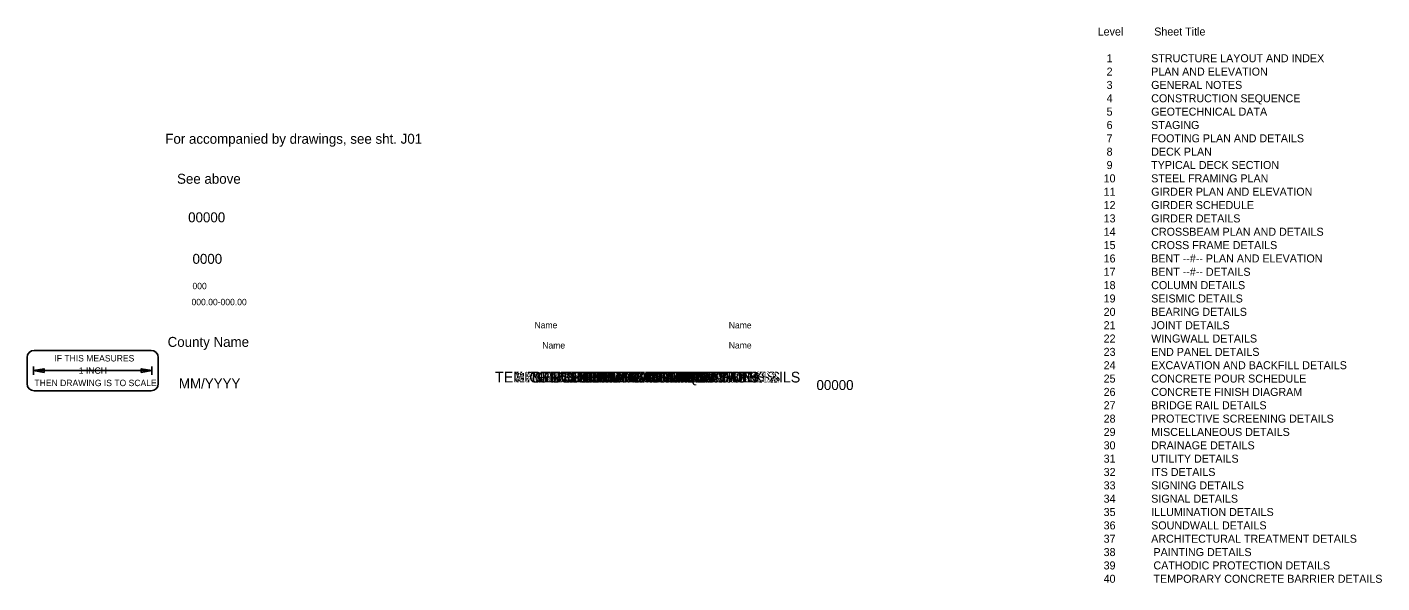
# Model space of a CAD drawing. Extents: x 0.799 to 1.751, y -0.088 to 0.302.
import ezdxf

# ---------------------------------------------------------------- set-up
doc = ezdxf.new("R2010")
doc.units = 0
for name, color, linetype in [('Level 1', 7, 'Continuous'), ('Level 10', 7, 'Continuous'), ('Level 11', 7, 'Continuous'), ('Level 12', 7, 'Continuous'), ('Level 13', 7, 'Continuous'), ('Level 14', 7, 'Continuous'), ('Level 15', 7, 'Continuous'), ('Level 16', 7, 'Continuous'), ('Level 17', 7, 'Continuous'), ('Level 18', 7, 'Continuous'), ('Level 19', 7, 'Continuous'), ('Level 2', 7, 'Continuous'), ('Level 20', 7, 'Continuous'), ('Level 21', 7, 'Continuous'), ('Level 22', 7, 'Continuous'), ('Level 23', 7, 'Continuous'), ('Level 24', 7, 'Continuous'), ('Level 25', 7, 'Continuous'), ('Level 26', 7, 'Continuous'), ('Level 27', 7, 'Continuous'), ('Level 28', 7, 'Continuous'), ('Level 29', 7, 'Continuous'), ('Level 3', 7, 'Continuous'), ('Level 30', 7, 'Continuous'), ('Level 31', 7, 'Continuous'), ('Level 32', 7, 'Continuous'), ('Level 33', 7, 'Continuous'), ('Level 34', 7, 'Continuous'), ('Level 35', 7, 'Continuous'), ('Level 36', 7, 'Continuous'), ('Level 37', 7, 'Continuous'), ('Level 38', 7, 'Continuous'), ('Level 39', 7, 'Continuous'), ('Level 4', 7, 'Continuous'), ('Level 40', 7, 'Continuous'), ('Level 5', 7, 'Continuous'), ('Level 6', 7, 'Continuous'), ('Level 62', 7, 'Continuous'), ('Level 7', 7, 'Continuous'), ('Level 8', 7, 'Continuous'), ('Level 9', 7, 'Continuous'), ('P_ODOT_PLAN_General', 7, 'Continuous'), ('P_ODOT_PLAN_TBBDSDwg', 7, 'Continuous'), ('P_ODOT_PLAN_TBBgStrInfo', 7, 'Continuous'), ('P_ODOT_PLAN_TBlock', 7, 'Continuous'), ('P_ODOT_PLAN_TBShtDwgNo', 7, 'Continuous'), ('P_ODOT_PLAN_TeamNames', 7, 'Continuous')]:
    doc.layers.add(name, color=color, linetype=linetype)

msp = doc.modelspace()

# ---------------------------------------------------------------- linework, layer by layer
at = {"layer": 'P_ODOT_PLAN_General'}
for p, q in [((0.7987, 0.07), (0.7987, 0.05167)), ((0.88587, 0.075), (0.8037, 0.075)), ((0.89087, 0.05167), (0.89087, 0.07)), ((0.80311, 0.06383), (0.80311, 0.05783)), ((0.80311, 0.06083), (0.88645, 0.06083)), ((0.80311, 0.06083), (0.80311, 0.06083)), ((0.88645, 0.06383), (0.88645, 0.05783)), ((0.88645, 0.06083), (0.88645, 0.06083)), ((0.8037, 0.04667), (0.88587, 0.04667))]:
    msp.add_line(p, q, dxfattribs=at)
for points in [[(0.80311, 0.06083), (0.81061, 0.06208), (0.81061, 0.05958)], [(0.88645, 0.06083), (0.87895, 0.05958), (0.87895, 0.06208)]]:
    msp.add_lwpolyline(points, close=True, dxfattribs=at)
for centre, start, end in [((0.8037, 0.07), 90, 180), ((0.88587, 0.07), 360, 90), ((0.8037, 0.05167), 180, 270), ((0.88587, 0.05167), 270, 360)]:
    msp.add_arc(centre, 0.005, start, end, dxfattribs=at)

# ---------------------------------------------------------------- texts
at = {"layer": 'Level 1'}
msp.add_text('STRUCTURE LAYOUT AND INDEX', height=0.0075, dxfattribs=at).set_placement((1.1535, 0.0525))
at = {"layer": 'Level 10'}
msp.add_text('STEEL FRAMING PLAN', height=0.0075, dxfattribs=at).set_placement((1.17772, 0.0525))
at = {"layer": 'Level 11'}
msp.add_text('GIRDER PLAN AND ELEVATION', height=0.0075, dxfattribs=at).set_placement((1.15768, 0.0525))
at = {"layer": 'Level 12'}
msp.add_text('GIRDER SCHEDULE', height=0.0075, dxfattribs=at).set_placement((1.18503, 0.0525))
at = {"layer": 'Level 13'}
msp.add_text('GIRDER DETAILS', height=0.0075, dxfattribs=at).set_placement((1.19064, 0.0525))
at = {"layer": 'Level 14'}
msp.add_text('CROSSBEAM PLAN AND DETAILS', height=0.0075, dxfattribs=at).set_placement((1.15166, 0.0525))
at = {"layer": 'Level 15'}
msp.add_text('CROSS FRAME DETAILS', height=0.0075, dxfattribs=at).set_placement((1.17397, 0.0525))
at = {"layer": 'Level 16'}
msp.add_text('BENT   #   PLAN AND ELEVATION', height=0.0075, dxfattribs=at).set_placement((1.15357, 0.0525))
at = {"layer": 'Level 17'}
msp.add_text('BENT   #   DETAILS', height=0.0075, dxfattribs=at).set_placement((1.18653, 0.0525))
at = {"layer": 'Level 18'}
msp.add_text('COLUMN DETAILS', height=0.0075, dxfattribs=at).set_placement((1.1885, 0.0525))
at = {"layer": 'Level 19'}
msp.add_text('SEISMIC DETAILS', height=0.0075, dxfattribs=at).set_placement((1.18948, 0.0525))
at = {"layer": 'Level 2'}
msp.add_text('PLAN AND ELEVATION', height=0.0075, dxfattribs=at).set_placement((1.17813, 0.0525))
at = {"layer": 'Level 20'}
msp.add_text('BEARING DETAILS', height=0.0075, dxfattribs=at).set_placement((1.18747, 0.0525))
at = {"layer": 'Level 21'}
msp.add_text('JOINT DETAILS', height=0.0075, dxfattribs=at).set_placement((1.1961, 0.0525))
at = {"layer": 'Level 22'}
msp.add_text('WINGWALL DETAILS', height=0.0075, dxfattribs=at).set_placement((1.18198, 0.0525))
at = {"layer": 'Level 23'}
msp.add_text('END PANEL DETAILS', height=0.0075, dxfattribs=at).set_placement((1.18167, 0.0525))
at = {"layer": 'Level 24'}
msp.add_text('EXCAVATION AND BACKFILL DETAILS', height=0.0075, dxfattribs=at).set_placement((1.14188, 0.0525))
at = {"layer": 'Level 25'}
msp.add_text('CONCRETE POUR SCHEDULE', height=0.0075, dxfattribs=at).set_placement((1.16255, 0.0525))
at = {"layer": 'Level 26'}
msp.add_text('CONCRETE FINISH DIAGRAM', height=0.0075, dxfattribs=at).set_placement((1.16266, 0.0525))
at = {"layer": 'Level 27'}
msp.add_text('BRIDGE RAIL DETAILS', height=0.0075, dxfattribs=at).set_placement((1.17812, 0.0525))
at = {"layer": 'Level 28'}
msp.add_text('PROTECTIVE SCREENING DETAILS', height=0.0075, dxfattribs=at).set_placement((1.14986, 0.0525))
at = {"layer": 'Level 29'}
msp.add_text('MISCELLANEOUS DETAILS', height=0.0075, dxfattribs=at).set_placement((1.16834, 0.0525))
at = {"layer": 'Level 3'}
msp.add_text('GENERAL NOTES', height=0.0075, dxfattribs=at).set_placement((1.19067, 0.0525))
at = {"layer": 'Level 30'}
msp.add_text('DRAINAGE DETAILS', height=0.0075, dxfattribs=at).set_placement((1.18381, 0.0525))
at = {"layer": 'Level 31'}
msp.add_text('UTILITY DETAILS', height=0.0075, dxfattribs=at).set_placement((1.19204, 0.0525))
at = {"layer": 'Level 32'}
msp.add_text('ITS DETAILS', height=0.0075, dxfattribs=at).set_placement((1.20225, 0.0525))
at = {"layer": 'Level 33'}
msp.add_text('SIGNING DETAILS', height=0.0075, dxfattribs=at).set_placement((1.18893, 0.0525))
at = {"layer": 'Level 34'}
msp.add_text('SIGNAL DETAILS', height=0.0075, dxfattribs=at).set_placement((1.1915, 0.0525))
at = {"layer": 'Level 35'}
msp.add_text('ILLUMINATION DETAILS', height=0.0075, dxfattribs=at).set_placement((1.17469, 0.0525))
at = {"layer": 'Level 36'}
msp.add_text('SOUNDWALL DETAILS', height=0.0075, dxfattribs=at).set_placement((1.1782, 0.0525))
at = {"layer": 'Level 37'}
msp.add_text('ARCHITECTURAL TREAMENT DETAILS', height=0.0075, dxfattribs=at).set_placement((1.1414, 0.0525))
at = {"layer": 'Level 38'}
msp.add_text('PAINTING DETAILS', height=0.0075, dxfattribs=at).set_placement((1.18628, 0.0525))
at = {"layer": 'Level 39'}
msp.add_text('CATHODIC PROTECTION DETAILS', height=0.0075, dxfattribs=at).set_placement((1.15215, 0.0525))
at = {"layer": 'Level 4'}
msp.add_text('CONSTRUCTION SEQUENCE', height=0.0075, dxfattribs=at).set_placement((1.16569, 0.0525))
at = {"layer": 'Level 40'}
msp.add_text('TEMPORARY CONCRETE BARRIER DETAILS', height=0.0075, dxfattribs=at).set_placement((1.12764, 0.0525))
at = {"layer": 'Level 5'}
msp.add_text('GEOTECHNICAL DATA', height=0.0075, dxfattribs=at).set_placement((1.17923, 0.0525))
at = {"layer": 'Level 6'}
msp.add_text('STAGING', height=0.0075, dxfattribs=at).set_placement((1.2099, 0.0525))
at = {"layer": 'Level 62'}
msp.add_text('For accompanied by drawings, see sht. J01', height=0.007, dxfattribs=at).set_placement((0.89583, 0.22017))
at = {"layer": 'Level 7'}
msp.add_text('FOOTING PLAN AND DETAILS', height=0.0075, dxfattribs=at).set_placement((1.16133, 0.0525))
at = {"layer": 'Level 8'}
msp.add_text('DECK PLAN', height=0.0075, dxfattribs=at).set_placement((1.20362, 0.0525))
at = {"layer": 'Level 9'}
msp.add_text('TYPICAL DECK SECTION', height=0.0075, dxfattribs=at).set_placement((1.17436, 0.0525))
at = {"layer": 'P_ODOT_PLAN_General'}
for s, p in [('IF THIS MEASURES ', (0.8179, 0.06725)), ('1 INCH', (0.83505, 0.05858)), ('THEN DRAWING IS TO SCALE', (0.80386, 0.04992))]:
    msp.add_text(s, height=0.0045, dxfattribs=at).set_placement(p)
at = {"layer": 'P_ODOT_PLAN_TBBDSDwg'}
for s, p in [('See above', (0.9041, 0.19208)), ('00000', (0.9119, 0.165)), ('0000', (0.91498, 0.13583))]:
    msp.add_text(s, height=0.007, dxfattribs=at).set_placement(p)
at = {"layer": 'P_ODOT_PLAN_TBBgStrInfo'}
for s, p in [('County Name', (0.89749, 0.0775)), ('MM/YYYY', (0.90542, 0.04833))]:
    msp.add_text(s, height=0.007, dxfattribs=at).set_placement(p)
at = {"layer": 'P_ODOT_PLAN_TBlock'}
for s, height, p in [('Level', 0.005625, (1.55122, 0.29618)), ('Sheet Title', 0.005625, (1.59098, 0.29618)), ('   1             STRUCTURE LAYOUT AND INDEX', 0.005625, (1.55122, 0.27743)), ('   2             PLAN AND ELEVATION', 0.005625, (1.55122, 0.26805)), ('   3             GENERAL NOTES', 0.005625, (1.55122, 0.25868)), ('   4             CONSTRUCTION SEQUENCE', 0.005625, (1.55122, 0.2493)), ('   5             GEOTECHNICAL DATA', 0.005625, (1.55122, 0.23993)), ('   6             STAGING', 0.005625, (1.55122, 0.23055)), ('   7             FOOTING PLAN AND DETAILS', 0.005625, (1.55122, 0.22118)), ('   8             DECK PLAN', 0.005625, (1.55122, 0.2118)), ('   9             TYPICAL DECK SECTION', 0.005625, (1.55122, 0.20243)), ('  10            STEEL FRAMING PLAN', 0.005625, (1.55122, 0.19305)), ('  11            GIRDER PLAN AND ELEVATION', 0.005625, (1.55122, 0.18368)), ('  12            GIRDER SCHEDULE', 0.005625, (1.55122, 0.1743)), ('  13            GIRDER DETAILS', 0.005625, (1.55122, 0.16493)), ('  14            CROSSBEAM PLAN AND DETAILS', 0.005625, (1.55122, 0.15555)), ('  15            CROSS FRAME DETAILS', 0.005625, (1.55122, 0.14618)), ('  16            BENT --#-- PLAN AND ELEVATION', 0.005625, (1.55122, 0.1368)), ('  17            BENT --#-- DETAILS', 0.005625, (1.55122, 0.12743)), ('000', 0.0045, (0.91493, 0.118)), ('  18            COLUMN DETAILS', 0.005625, (1.55122, 0.11805)), ('  19            SEISMIC DETAILS', 0.005625, (1.55122, 0.10868)), ('000.00-000.00', 0.0045, (0.91427, 0.10675)), ('  20            BEARING DETAILS', 0.005625, (1.55122, 0.0993)), ('  21            JOINT DETAILS', 0.005625, (1.55122, 0.08993)), ('  22            WINGWALL DETAILS', 0.005625, (1.55122, 0.08055)), ('  23            END PANEL DETAILS', 0.005625, (1.55122, 0.07118)), ('  24            EXCAVATION AND BACKFILL DETAILS', 0.005625, (1.55122, 0.0618)), ('  25            CONCRETE POUR SCHEDULE', 0.005625, (1.55122, 0.05243)), ('  26            CONCRETE FINISH DIAGRAM', 0.005625, (1.55122, 0.04305)), ('  27            BRIDGE RAIL DETAILS', 0.005625, (1.55122, 0.03368)), ('  28            PROTECTIVE SCREENING DETAILS', 0.005625, (1.55122, 0.0243)), ('  29            MISCELLANEOUS DETAILS', 0.005625, (1.55122, 0.01493)), ('  30            DRAINAGE DETAILS', 0.005625, (1.55122, 0.00555)), ('  31            UTILITY DETAILS', 0.005625, (1.55122, -0.00382)), ('  32            ITS DETAILS', 0.005625, (1.55122, -0.0132)), ('  33            SIGNING DETAILS', 0.005625, (1.55122, -0.02257)), ('  34            SIGNAL DETAILS', 0.005625, (1.55122, -0.03195)), ('  35            ILLUMINATION DETAILS', 0.005625, (1.55122, -0.04132)), ('  36            SOUNDWALL DETAILS', 0.005625, (1.55122, -0.0507)), ('  37            ARCHITECTURAL TREATMENT DETAILS', 0.005625, (1.55122, -0.06007)), ('  38', 0.005625, (1.55122, -0.06945)), ('        PAINTING DETAILS', 0.005625, (1.57372, -0.06945)), ('  39', 0.005625, (1.55122, -0.07882)), ('        CATHODIC PROTECTION DETAILS', 0.005625, (1.57372, -0.07882)), ('  40', 0.005625, (1.55122, -0.0882)), ('        TEMPORARY CONCRETE BARRIER DETAILS', 0.005625, (1.57372, -0.0882))]:
    msp.add_text(s, height=height, dxfattribs=at).set_placement(p)
at = {"layer": 'P_ODOT_PLAN_TBShtDwgNo'}
msp.add_text('00000', height=0.007, dxfattribs=at).set_placement((1.35357, 0.04719))
at = {"layer": 'P_ODOT_PLAN_TeamNames'}
for p in [(1.15533, 0.09053), (1.2919, 0.09048), (1.16081, 0.07633), (1.2919, 0.07637)]:
    msp.add_text('Name', height=0.0045, dxfattribs=at).set_placement(p)

doc.saveas('drawing.dxf')
